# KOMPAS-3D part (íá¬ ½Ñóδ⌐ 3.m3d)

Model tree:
1. Эскиз:1
2. Операция выдавливания:1
     Расстояние 1 = 10
3. Скругление:1
     Радиус = 1
4. Скругление:2
     Радиус = 2
5. Эскиз:2
6. Вырезать элемент выдавливания:1
     Расстояние 1 = 0.2
7. Скругление:3
     Радиус = 0.1
8. Эскиз:3
9. Операция выдавливания:2
     Расстояние 1 = 2; Расстояние 2 = 4.9
10. Скругление:4
     Радиус = 1
11. Эскиз:4
12. Вырезать элемент выдавливания:2
     Расстояние 1 = 0.2
13. Скругление:5
     Радиус = 0.1
14. Эскиз:5
15. Операция выдавливания:3
     Расстояние 1 = 0.1; Расстояние 2 = 4.9

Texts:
  бак левый 3
  Сплав АЛ8  ГОСТ 1583-93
